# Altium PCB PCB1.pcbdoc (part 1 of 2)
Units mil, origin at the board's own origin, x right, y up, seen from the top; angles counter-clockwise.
Board outline 4205 x 5050 mil, 2 copper layers (Top Layer, Bottom Layer); 96 components, 86 nets, 386 pads, 487 vias.
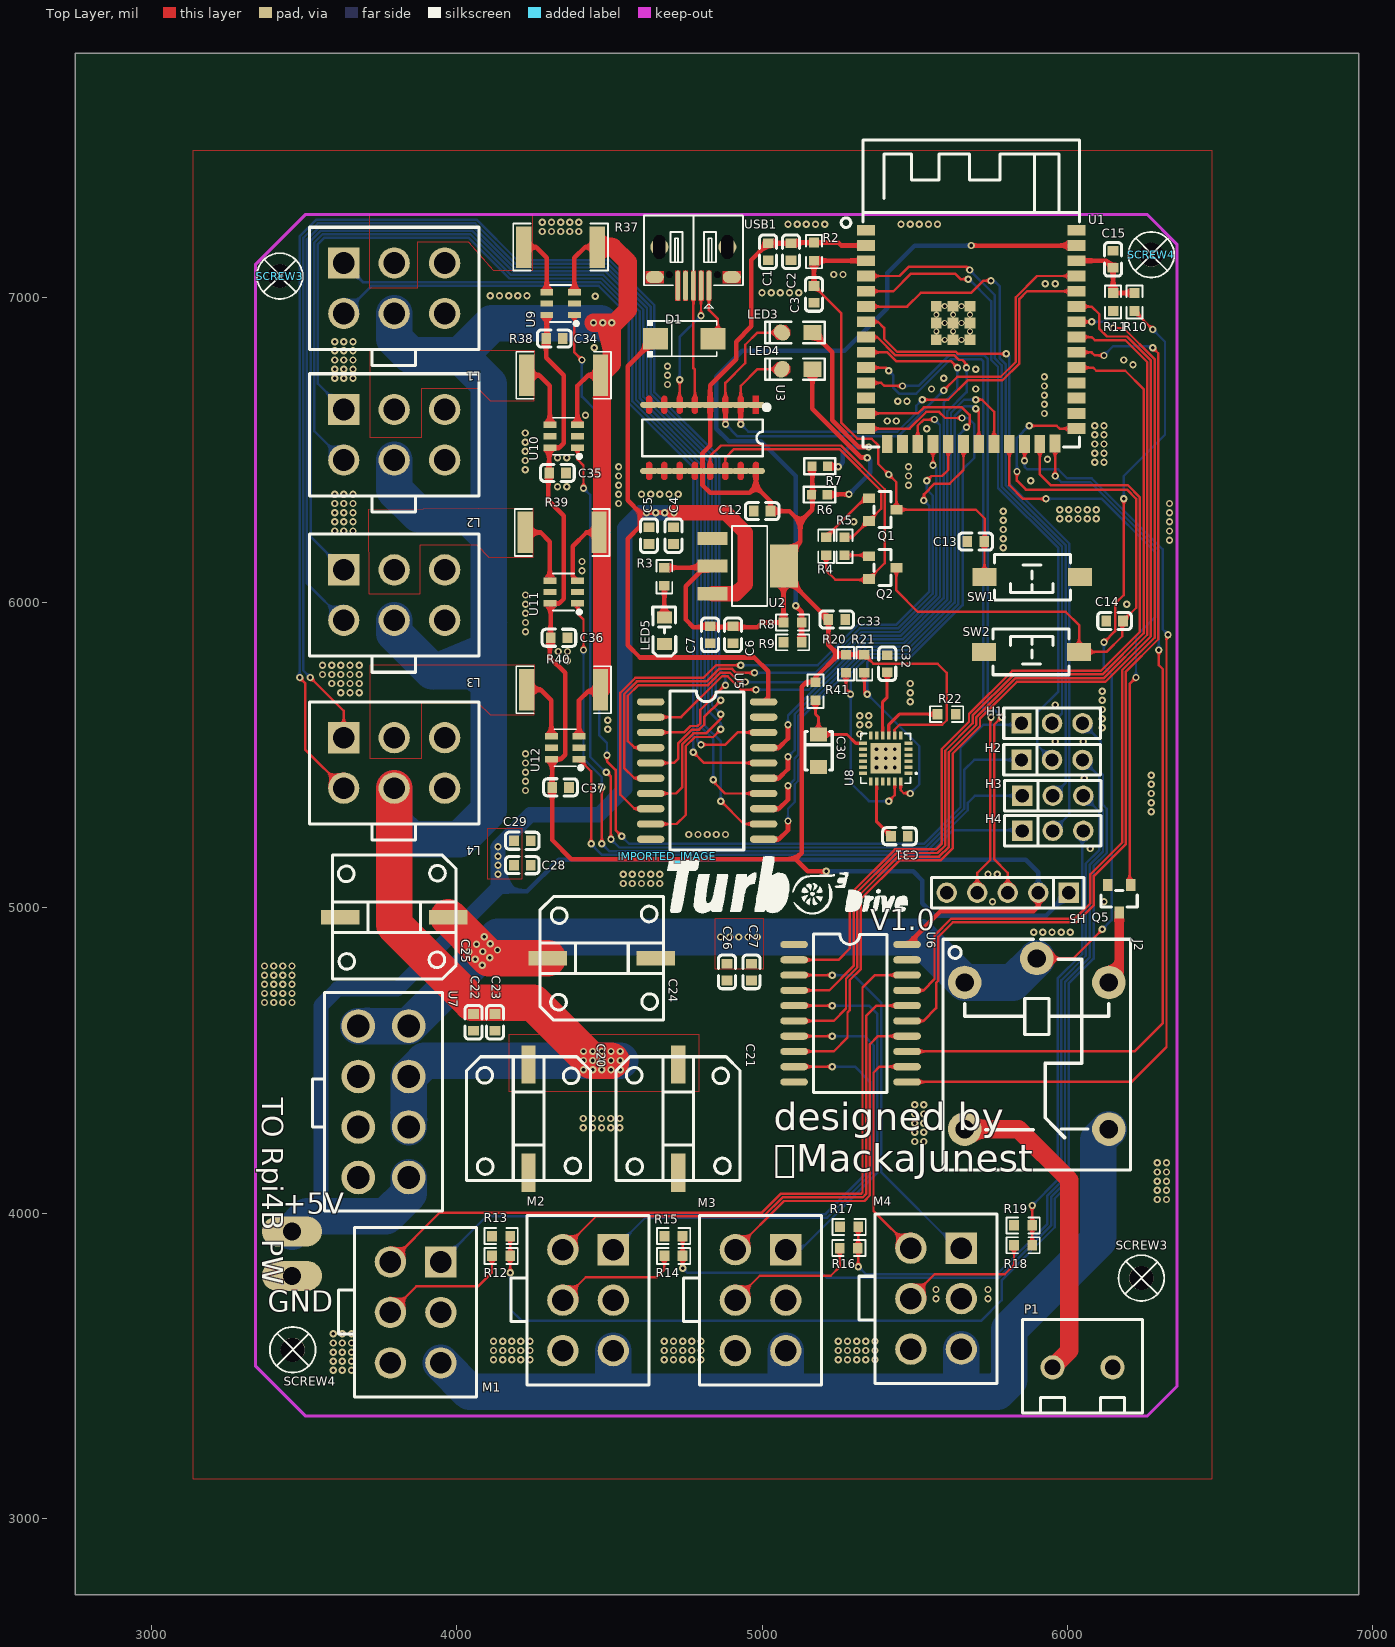
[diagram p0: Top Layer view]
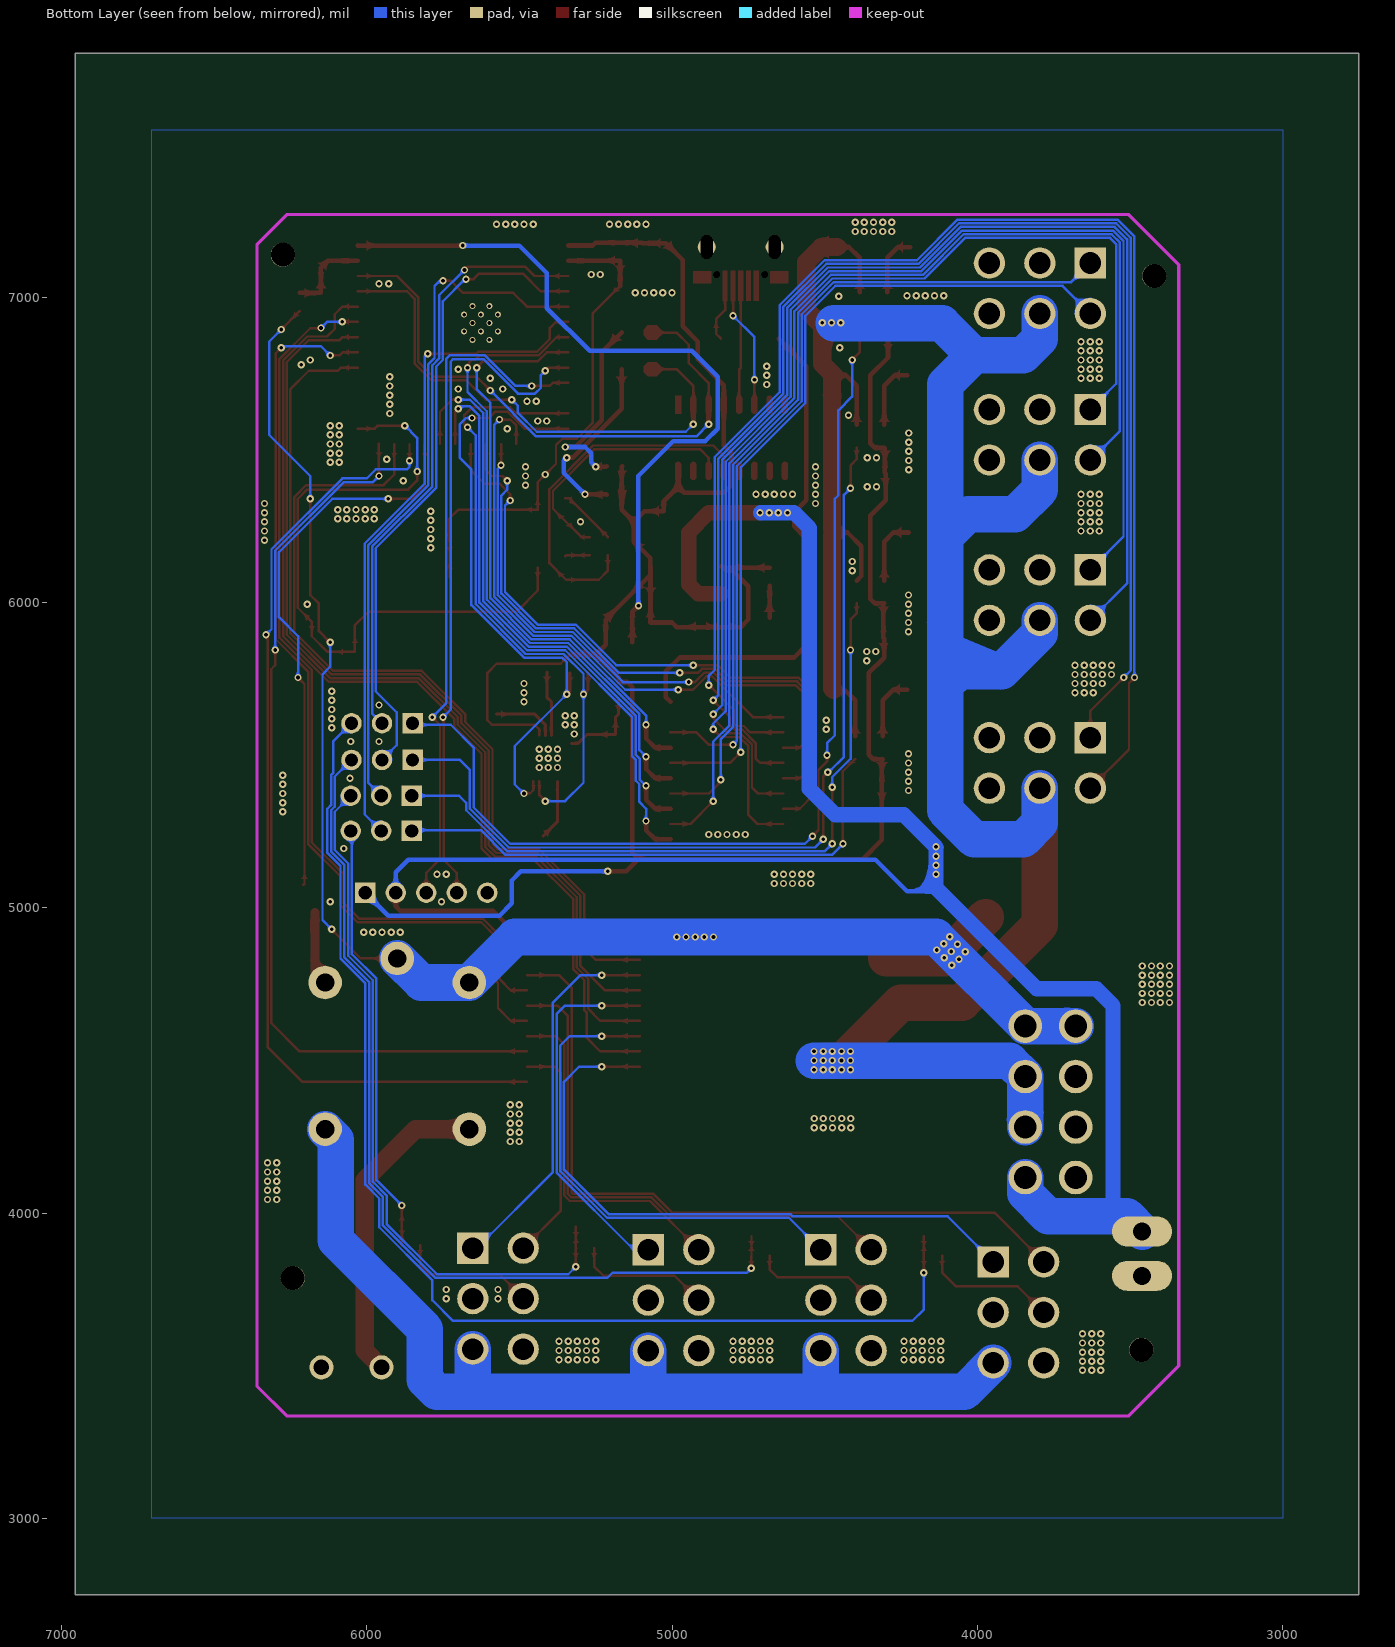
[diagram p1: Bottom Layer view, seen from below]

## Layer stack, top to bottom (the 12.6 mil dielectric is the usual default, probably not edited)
Top Layer: signal copper (thickness not stored)
Dielectric: dielectric 12.6, FR-4, Dk 4.8
Bottom Layer: signal copper (thickness not stored)

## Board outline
6955,2750 2750,2750 2750,7800 6955,7800

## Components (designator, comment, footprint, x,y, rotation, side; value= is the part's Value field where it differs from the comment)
C1 "={Value}/50V" C0603 5020,7150 r90 top
C2 "={Value}/50v" C0603 5095,7150 r90 top
C3 "CAP_0603" C0603 5170,7010 r90 top
C4 "CAP_0603" C0603 4710,6220 r90 top
C5 "CAP_0603" C0603 4630,6220 r90 top
C6 "CAP_0603" C0603 4905,5895 r90 top
C7 "CAP_0603" C0603 4830,5895 r90 top
C12 "CAP_0603" C0603 5000,6300 r180 top
C13 "CAP_0603" C0603 5700,6200 r0 top
C14 "CAP_0603" C0603 6155,5940 r0 top
C15 "CAP_0603" C0603 6150,7125 r90 top
C20 "330uf" CAP-T-10*10.5 4235,4310 r270 top
C21 "330uf" CAP-T-10*10.5 4725,4310 r270 top
C22 "CAP_0603" C0603 4055,4625 r270 top
C23 "CAP_0603" C0603 4125,4625 r270 top
C24 "330uf" CAP-T-10*10.5 4475,4835 r0 top
C25 "330uf" CAP-T-10*10.5 3795,4970 r180 top
C26 "CAP_0603" C0603 4885,4790 r270 top
C27 "CAP_0603" C0603 4965,4790 r270 top
C28 "CAP_0603" C0603 4215,5140 r0 top
C29 "CAP_0603" C0603 4215,5220 r0 top
C30 "0.1uF/4v/104" CAP-SMD_L3.2-W1.6 5185,5515 r270 top
C31 "2.2nF/50V" C0603 5450,5235 r180 top
C32 "0.1uF/2v/104" C0603 5410,5800 r270 top
C33 "10nF/4v" C0603 5245,5945 r0 top
C34 "CAP_0603" C0603 4320,6865 r0 top
C35 "CAP_0603" C0603 4330,6425 r0 top
C36 "CAP_0603" C0603 4335,5885 r0 top
C37 "CAP_0603" C0603 4340,5395 r0 top
D1 "SS14(1N5819)-SMA" SMA_L4.3-W2.7-LS5.1-RD 4745,6865 r0 top
H1 "HDR-M_2.54_1x3P" HDR-TH_3P-P2.54-V-M 5950,5605 r0 top
H2 "HDR-M_2.54_1x3P" HDR-TH_3P-P2.54-V-M 5950,5485 r0 top
H3 "HDR-M_2.54_1x3P" HDR-TH_3P-P2.54-V-M 5952.5,5367.5 r0 top
H4 "HDR-M_2.54_1x3P" HDR-TH_3P-P2.54-V-M 5952.5,5252.5 r0 top
H5 "HDR-M_2.54_1x5P" HDR-TH_5P-P2.54-V-M 5805,5050 r180 top
IMPORTED_IMAGE "IMPORTED_IMAGE" IMPORTED_IMAGE 4690,5170 r0 top
J2 "EM_BRAKE1" RELAY-TH_SRD-XXVDC-XL-C 5900,4555 r270 top
L1 "5557-2*3A" CONN-TH_5557-2X3A 3795,7030 r180 top
L2 "5557-2*3A" CONN-TH_5557-2X3A 3795,6550 r180 top
L3 "5557-2*3A" CONN-TH_5557-2X3A 3795,6025 r180 top
L4 "5557-2*3A" CONN-TH_5557-2X3A 3795,5475 r180 top
LED3 "LED-BLUE" "LED 0805B" 5115,6885 r180 top
LED4 "LED-YELLOW" "LED 0805Y" 5115,6765 r180 top
LED5 "LED_0805-R" LED_0805 4680,5910 r90 top
M1 "5557-2*3A" CONN-TH_5557-2X3A 3865,3675 r90 top
M2 "5557-2*3A" CONN-TH_5557-2X3A 4430,3715 r90 top
M3 "5557-2*3A" CONN-TH_5557-2X3A 4995,3715 r90 top
M4 "5557-2*3A" CONN-TH_5557-2X3A 5570,3720 r90 top
P1 "WJ126V-5.0-2P" CONN-TH_WJ126V-5.0-2P 6050,3495 r90 top
Q1 "S8050_SOT_NPN" S8050_SOT-23 5395,6310 r180 top
Q2 "S8050_SOT_NPN" S8050_SOT-23 5395,6120 r180 top
Q5 "S8050_SOT_NPN" S8050_SOT-23 6175,5030 r90 top
R2 "Res_0603" R0603 5170,7150 r90 top
R3 "Res_0603" R0603 4680,6085 r270 top
R4 "Res_0603" R0603 5210,6185 r90 top
R5 "Res_0603" R0603 5270,6185 r270 top
R6 "1K" "R 0603_L" 5188.12,6353.78 r180 top
R7 "1K" "R 0603_L" 5188.78,6446.87 r180 top
R8 "KNTC0603/10KF3950" R0603 5100,5935 r180 top
R9 "Res_0603" R0603 5100,5870 r0 top
R10 "Res_0603" R0603 6220,6985 r90 top
R11 "Res_0603" R0603 6150,6985 r270 top
R12 "Res_0603" R0603 4145,3860 r0 top
R13 "Res_0603" R0603 4145,3925 r180 top
R14 "Res_0603" R0603 4710,3860 r0 top
R15 "Res_0603" R0603 4710,3925 r180 top
R16 "Res_0603" R0603 5284.34,3885.77 r0 top
R17 "Res_0603" R0603 5285,3955 r180 top
R18 "Res_0603" R0603 5855,3895 r0 top
R19 "Res_0603" R0603 5855,3960 r180 top
R20 "4.7k" R0603 5275,5800 r90 top
R21 "4.7k" R0603 5335,5800 r90 top
R22 "4.7k" R0603 5604.66,5634.66 r180 top
R37 "0.01" R2512 4340,7165 r0 top
R38 "0.01" R2512 4350,6745 r0 top
R39 "0.01" R2512 4345,6230 r0 top
R40 "0.01" R2512 4350,5715 r0 top
R41 "Res_0603" R0603 5175,5710 r90 top
SCREW3 "M2螺丝" M2螺丝 3420,7070 r0 top
SCREW3 "M2螺丝" M2螺丝 6242.5,3787.5 r0 top
SCREW4 "M2螺丝" M2螺丝 6275,7140 r0 top
SCREW4 "M2螺丝" M2螺丝 3462.5,3552.5 r0 top
SW1 "3x6x5" "TSW SMD-3*6*2.5" 5883.65,6083.65 r180 top
SW2 "3x6x5" "TSW SMD-3*6*2.5" 5883.65,5838.65 r0 top
U1 "ESP32-S3-WROOM-1-N16R8" WIRELM-SMD_ESP32-S3-WROOM-1 5685,6870 r0 top
U2 "AMS1117-3.3_C6186" SOT-223-3_L6.5-W3.4-P2.30-LS7.0-BR 4955,6120 r180 top
U3 "CH340C" SOP16_L 4805,6540 r270 top
U5 "SN74HC244DWR" SOIC-20_L13.0-W7.6-P1.27-LS10.6-BL 4820,5450 r270 top
U6 "SN74HC244DWR" SOIC-20_L13.0-W7.6-P1.27-LS10.6-BL 5290,4655 r270 top
U7 "5557-2*4P直针座-黑色8芯" CONN-TH_5557-2-4P 3760,4365 r270 top
U8 "MPU-6050_C24112" QFN-24_L4.0-W4.0-P0.50-BL-EP2.6 5405,5490 r90 top
U9 "INA181A2IDBVR" SOT-23-6_L2.9-W1.6-P0.95-LS2.8-BL 4340,6980 r90 top
U10 "INA181A2IDBVR" SOT-23-6_L2.9-W1.6-P0.95-LS2.8-BL 4350,6545 r90 top
U11 "INA181A2IDBVR" SOT-23-6_L2.9-W1.6-P0.95-LS2.8-BL 4350,6035 r90 top
U12 "INA181A2IDBVR" SOT-23-6_L2.9-W1.6-P0.95-LS2.8-BL 4355,5525 r90 top
USB1 "MICRO USB" USB-MICRO_B 4775,7165 r180 top

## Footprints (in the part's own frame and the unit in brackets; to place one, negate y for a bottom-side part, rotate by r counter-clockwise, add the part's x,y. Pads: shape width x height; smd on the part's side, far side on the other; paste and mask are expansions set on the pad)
C0603 [mm]
  rect 0.8x0.9 smd: 1(-0.7,0) 2(0.7,0)
  silkscreen extent -1.41,-0.71 1.39,0.72
CAP-SMD_L3.2-W1.6 [mm]
  rect 1.2x1.4 smd: 1(-1.35,0) 2(1.35,0)
  silkscreen extent -1.6,-1.14 1.6,1.14
CAP-T-10*10.5 [mm]
  rect 3.2x1.2 smd: 1(-4.5,0) 2(4.5,0)
  silkscreen extent -5.15,-5.15 5.15,5.15
CONN-TH_5557-2-4P [mm]
  round 2.8 hole 1.9: 1(-6.3,2.1) 2(-2.1,2.1) 3(2.1,2.1) 4(6.3,2.1) 5(6.3,-2.1) 6(2.1,-2.1) 7(-2.1,-2.1) 8(-6.3,-2.1)
  silkscreen extent -9.1,-5.9 9.1,4.9
CONN-TH_5557-2X3A [mm]
  rect 2.6x2.6 hole 1.8: 1(4.2,-2.1)
  round 2.6 hole 1.8: 2(0,-2.1) 3(-4.2,-2.1) 5(0,2.1)
  round 2.6 hole 1.8 copper offset 0,0: 4(4.2,2.1) 6(-4.2,2.1)
  silkscreen extent -7.05,-5.08 7.05,6.42
CONN-TH_WJ126V-5.0-2P [mm]
  round 2 hole 1.3: 1(0,2.501) 2(0,-2.501)
  silkscreen extent -3.8,-5 4,5
HDR-TH_3P-P2.54-V-M [mm]
  rect 1.7x1.7 hole 1.1: 1(-2.54,0)
  round 1.7 hole 1.1: 2(0,0) 3(2.54,0)
  silkscreen extent -4.02,-1.27 4.02,1.27
HDR-TH_5P-P2.54-V-M [mm]
  rect 1.7x1.7 hole 1.1: 1(-5.08,0)
  round 1.7 hole 1.1: 2(-2.54,0) 3(0,0) 4(2.54,0) 5(5.08,0)
  silkscreen extent -6.35,-1.27 6.35,1.27
IMPORTED_IMAGE [mil]
  silkscreen extent 0,-191 787,0
"LED 0805B" [mil]
  rect 60x50 smd: 1(-50,0)
  oval 56.19x46.19 smd rot 140: 2(50,0)
  Top Layer region: 35.43,23.1 21.9,9.57 21.9,-9.57 35.43,-23.1 64.57,-23.1 78.1,-9.57 78.1,9.57 64.57,23.1
  silkscreen extent -90,-35 105,35
"LED 0805Y" [mil]
  rect 60x50 smd: 1(-50,0)
  oval 56.19x46.19 smd rot 60: 2(50,0)
  Top Layer region: 35.43,23.1 21.9,9.57 21.9,-9.57 35.43,-23.1 64.57,-23.1 78.1,-9.57 78.1,9.57 64.57,23.1
  silkscreen extent -90,-35 105,35
LED_0805 [mm]
  rect 1x1.25 smd: 1(-1.15,0.005) 2(1.05,0.005)
  silkscreen extent -2.15,-0.94 1.93,0.97
M2螺丝 [mm]
  round 2 hole 2: 1(0,0)
  silkscreen extent -1.9,-1.9 1.9,1.9
QFN-24_L4.0-W4.0-P0.50-BL-EP2.6 [mm]
  rect 0.28x0.665 smd: 1(-1.25,-1.908) 2(-0.75,-1.908) 3(-0.25,-1.908) 4(0.25,-1.908) 5(0.75,-1.908) 6(1.25,-1.908) 13(1.25,1.908) 14(0.75,1.908) 15(0.25,1.908) 16(-0.25,1.908) 17(-0.75,1.908) 18(-1.25,1.908)
  rect 0.665x0.28 smd: 7(1.908,-1.25) 8(1.908,-0.75) 9(1.908,-0.25) 10(1.908,0.25) 11(1.908,0.75) 12(1.908,1.25) 19(-1.908,1.25) 20(-1.908,0.75) 21(-1.908,0.25) 22(-1.908,-0.25) 23(-1.908,-0.75) 24(-1.908,-1.25)
  rect 2.55x2.55 smd: 25(0,0)
  silkscreen extent -2.08,-2.61 2.08,2.08
R0603 [mil]
  rect 31.75x34.02 smd: 1(-29.66,0) 2(29.66,0)
  silkscreen extent -55,-26 55,26
R2512 [mil]
  rect 50.49x136.06 smd: 1(-120.72,0) 2(120.72,0)
  silkscreen extent -155,-77 155,77
"R 0603_L" [mil]
  rect 30x30 smd: 1(-25.59,0) 2(25.59,0)
  silkscreen extent -51,-26 51,26
RELAY-TH_SRD-XXVDC-XL-C [mil]
  round 110 hole 60: 1(-200.79,-236.22) 2(279.53,-236.19) 3(279.53,236.2) 4(-200.79,236.22) 5(-279.53,0)
  silkscreen extent -342,-307 413,307
S8050_SOT-23 [mm]
  rect 1x0.8 smd: 1(1.15,-0.823) 2(1.15,1.077) 3(-1.15,0.127)
  silkscreen extent -0.7,-1.37 0.7,1.63
SMA_L4.3-W2.7-LS5.1-RD [mm]
  rect 2.1x1.8 smd: 1(-2.4,0) 2(2.4,0)
  silkscreen extent -3.08,-1.54 2.7,1.54
SOIC-20_L13.0-W7.6-P1.27-LS10.6-BL [mm]
  oval 0.6x2.3 smd: 1(-5.715,-4.7) 2(-4.445,-4.7) 3(-3.175,-4.7) 4(-1.905,-4.7) 5(-0.635,-4.7) 6(0.635,-4.7) 7(1.905,-4.7) 8(3.175,-4.7) 9(4.445,-4.7) 10(5.715,-4.7) 11(5.715,4.7) 12(4.445,4.7) 13(3.175,4.7) 14(1.905,4.7) 15(0.635,4.7) 16(-0.635,4.7) 17(-1.905,4.7) 18(-3.175,4.7) 19(-4.445,4.7) 20(-5.715,4.7)
  silkscreen extent -6.6,-3.1 6.6,3.05
SOP16_L [mm]
  oval 0.5x1.5 smd: 1(-2.752,4.445)
  oval 0.5x1.499 smd: 2(-2.752,3.175) 3(-2.752,1.905) 4(-2.752,0.635) 5(-2.752,-0.635) 6(-2.752,-1.905) 7(-2.752,-3.175) 8(-2.752,-4.445) 9(2.752,-4.445) 10(2.752,-3.175) 11(2.752,-1.905) 12(2.752,-0.635) 13(2.752,0.635) 14(2.752,1.905) 15(2.752,3.175) 16(2.752,4.445)
  Top Layer region: 3.252,-1.655 3.277,-1.656 3.302,-1.66 3.327,-1.666 3.351,-1.675 3.373,-1.686 3.395,-1.7 3.415,-1.715 3.433,-1.733 3.45,-1.752 3.464,-1.773 3.476,-1.795 3.486,-1.818 3.494,-1.842 3.499,-1.867 3.502,-1.892 3.502,-1.918 3.499,-1.943 3.494,-1.968 3.486,-1.992 3.476,-2.015 3.464,-2.037 3.45,-2.058 3.433,-2.077 3.415,-2.095 3.395,-2.11 3.373,-2.124 3.351,-2.135 3.327,-2.144 3.302,-2.15 3.277,-2.154 3.252,-2.155 2.252,-2.155 2.227,-2.154 2.202,-2.15 2.177,-2.144 2.153,-2.135 2.131,-2.124 2.109,-2.11 2.089,-2.095 2.071,-2.077 2.054,-2.058 2.04,-2.037 2.028,-2.015 2.018,-1.992 2.01,-1.968 2.005,-1.943 2.002,-1.918 2.002,-1.892 2.005,-1.867 2.01,-1.842 2.018,-1.818 2.028,-1.795 2.04,-1.773 2.054,-1.752 2.071,-1.733 2.089,-1.715 2.109,-1.7 2.131,-1.686 2.153,-1.675 2.177,-1.666 2.202,-1.66 2.227,-1.656 2.252,-1.655
  Top Layer region: 3.252,-2.925 3.277,-2.926 3.302,-2.93 3.327,-2.936 3.351,-2.945 3.373,-2.956 3.395,-2.97 3.415,-2.985 3.433,-3.003 3.45,-3.022 3.464,-3.043 3.476,-3.065 3.486,-3.088 3.494,-3.112 3.499,-3.137 3.502,-3.162 3.502,-3.188 3.499,-3.213 3.494,-3.238 3.486,-3.262 3.476,-3.285 3.464,-3.307 3.45,-3.328 3.433,-3.347 3.415,-3.365 3.395,-3.38 3.373,-3.394 3.351,-3.405 3.327,-3.414 3.302,-3.42 3.277,-3.424 3.252,-3.425 2.252,-3.425 2.227,-3.424 2.202,-3.42 2.177,-3.414 2.153,-3.405 2.131,-3.394 2.109,-3.38 2.089,-3.365 2.071,-3.347 2.054,-3.328 2.04,-3.307 2.028,-3.285 2.018,-3.262 2.01,-3.238 2.005,-3.213 2.002,-3.188 2.002,-3.162 2.005,-3.137 2.01,-3.112 2.018,-3.088 2.028,-3.065 2.04,-3.043 2.054,-3.022 2.071,-3.003 2.089,-2.985 2.109,-2.97 2.131,-2.956 2.153,-2.945 2.177,-2.936 2.202,-2.93 2.227,-2.926 2.252,-2.925
  Top Layer region: 3.252,-0.385 3.277,-0.386 3.302,-0.39 3.327,-0.396 3.351,-0.405 3.373,-0.416 3.395,-0.43 3.415,-0.445 3.433,-0.463 3.45,-0.482 3.464,-0.503 3.476,-0.525 3.486,-0.548 3.494,-0.572 3.499,-0.597 3.502,-0.622 3.502,-0.648 3.499,-0.673 3.494,-0.698 3.486,-0.722 3.476,-0.745 3.464,-0.767 3.45,-0.788 3.433,-0.807 3.415,-0.825 3.395,-0.84 3.373,-0.854 3.351,-0.865 3.327,-0.874 3.302,-0.88 3.277,-0.884 3.252,-0.885 2.252,-0.885 2.227,-0.884 2.202,-0.88 2.177,-0.874 2.153,-0.865 2.131,-0.854 2.109,-0.84 2.089,-0.825 2.071,-0.807 2.054,-0.788 2.04,-0.767 2.028,-0.745 2.018,-0.722 2.01,-0.698 2.005,-0.673 2.002,-0.648 2.002,-0.622 2.005,-0.597 2.01,-0.572 2.018,-0.548 2.028,-0.525 2.04,-0.503 2.054,-0.482 2.071,-0.463 2.089,-0.445 2.109,-0.43 2.131,-0.416 2.153,-0.405 2.177,-0.396 2.202,-0.39 2.227,-0.386 2.252,-0.385
  Top Layer region: 3.252,-4.195 3.277,-4.196 3.302,-4.2 3.327,-4.206 3.351,-4.215 3.373,-4.226 3.395,-4.24 3.415,-4.255 3.433,-4.273 3.45,-4.292 3.464,-4.313 3.476,-4.335 3.486,-4.358 3.494,-4.382 3.499,-4.407 3.502,-4.432 3.502,-4.458 3.499,-4.483 3.494,-4.508 3.486,-4.532 3.476,-4.555 3.464,-4.577 3.45,-4.598 3.433,-4.617 3.415,-4.635 3.395,-4.65 3.373,-4.664 3.351,-4.675 3.327,-4.684 3.302,-4.69 3.277,-4.694 3.252,-4.695 2.252,-4.695 2.227,-4.694 2.202,-4.69 2.177,-4.684 2.153,-4.675 2.131,-4.664 2.109,-4.65 2.089,-4.635 2.071,-4.617 2.054,-4.598 2.04,-4.577 2.028,-4.555 2.018,-4.532 2.01,-4.508 2.005,-4.483 2.002,-4.458 2.002,-4.432 2.005,-4.407 2.01,-4.382 2.018,-4.358 2.028,-4.335 2.04,-4.313 2.054,-4.292 2.071,-4.273 2.089,-4.255 2.109,-4.24 2.131,-4.226 2.153,-4.215 2.177,-4.206 2.202,-4.2 2.227,-4.196 2.252,-4.195
  Top Layer region: 3.252,0.885 3.277,0.884 3.302,0.88 3.327,0.874 3.351,0.865 3.373,0.854 3.395,0.84 3.415,0.825 3.433,0.807 3.45,0.788 3.464,0.767 3.476,0.745 3.486,0.722 3.494,0.698 3.499,0.673 3.502,0.648 3.502,0.622 3.499,0.597 3.494,0.572 3.486,0.548 3.476,0.525 3.464,0.503 3.45,0.482 3.433,0.463 3.415,0.445 3.395,0.43 3.373,0.416 3.351,0.405 3.327,0.396 3.302,0.39 3.277,0.386 3.252,0.385 2.252,0.385 2.227,0.386 2.202,0.39 2.177,0.396 2.153,0.405 2.131,0.416 2.109,0.43 2.089,0.445 2.071,0.463 2.054,0.482 2.04,0.503 2.028,0.525 2.018,0.548 2.01,0.572 2.005,0.597 2.002,0.622 2.002,0.648 2.005,0.673 2.01,0.698 2.018,0.722 2.028,0.745 2.04,0.767 2.054,0.788 2.071,0.807 2.089,0.825 2.109,0.84 2.131,0.854 2.153,0.865 2.177,0.874 2.202,0.88 2.227,0.884 2.252,0.885
  Top Layer region: 3.252,2.155 3.277,2.154 3.302,2.15 3.327,2.144 3.351,2.135 3.373,2.124 3.395,2.11 3.415,2.095 3.433,2.077 3.45,2.058 3.464,2.037 3.476,2.015 3.486,1.992 3.494,1.968 3.499,1.943 3.502,1.918 3.502,1.892 3.499,1.867 3.494,1.842 3.486,1.818 3.476,1.795 3.464,1.773 3.45,1.752 3.433,1.733 3.415,1.715 3.395,1.7 3.373,1.686 3.351,1.675 3.327,1.666 3.302,1.66 3.277,1.656 3.252,1.655 2.252,1.655 2.227,1.656 2.202,1.66 2.177,1.666 2.153,1.675 2.131,1.686 2.109,1.7 2.089,1.715 2.071,1.733 2.054,1.752 2.04,1.773 2.028,1.795 2.018,1.818 2.01,1.842 2.005,1.867 2.002,1.892 2.002,1.918 2.005,1.943 2.01,1.968 2.018,1.992 2.028,2.015 2.04,2.037 2.054,2.058 2.071,2.077 2.089,2.095 2.109,2.11 2.131,2.124 2.153,2.135 2.177,2.144 2.202,2.15 2.227,2.154 2.252,2.155
  Top Layer region: -2.252,-4.195 -2.227,-4.196 -2.202,-4.2 -2.177,-4.206 -2.153,-4.215 -2.131,-4.226 -2.109,-4.24 -2.089,-4.255 -2.071,-4.273 -2.054,-4.292 -2.04,-4.313 -2.028,-4.335 -2.018,-4.358 -2.01,-4.382 -2.005,-4.407 -2.002,-4.432 -2.002,-4.458 -2.005,-4.483 -2.01,-4.508 -2.018,-4.532 -2.028,-4.555 -2.04,-4.577 -2.054,-4.598 -2.071,-4.617 -2.089,-4.635 -2.109,-4.65 -2.131,-4.664 -2.153,-4.675 -2.177,-4.684 -2.202,-4.69 -2.227,-4.694 -2.252,-4.695 -3.252,-4.695 -3.277,-4.694 -3.302,-4.69 -3.327,-4.684 -3.351,-4.675 -3.373,-4.664 -3.395,-4.65 -3.415,-4.635 -3.433,-4.617 -3.45,-4.598 -3.464,-4.577 -3.476,-4.555 -3.486,-4.532 -3.494,-4.508 -3.499,-4.483 -3.502,-4.458 -3.502,-4.432 -3.499,-4.407 -3.494,-4.382 -3.486,-4.358 -3.476,-4.335 -3.464,-4.313 -3.45,-4.292 -3.433,-4.273 -3.415,-4.255 -3.395,-4.24 -3.373,-4.226 -3.351,-4.215 -3.327,-4.206 -3.302,-4.2 -3.277,-4.196 -3.252,-4.195
  Top Layer region: -2.252,-2.925 -2.227,-2.926 -2.202,-2.93 -2.177,-2.936 -2.153,-2.945 -2.131,-2.956 -2.109,-2.97 -2.089,-2.985 -2.071,-3.003 -2.054,-3.022 -2.04,-3.043 -2.028,-3.065 -2.018,-3.088 -2.01,-3.112 -2.005,-3.137 -2.002,-3.162 -2.002,-3.188 -2.005,-3.213 -2.01,-3.238 -2.018,-3.262 -2.028,-3.285 -2.04,-3.307 -2.054,-3.328 -2.071,-3.347 -2.089,-3.365 -2.109,-3.38 -2.131,-3.394 -2.153,-3.405 -2.177,-3.414 -2.202,-3.42 -2.227,-3.424 -2.252,-3.425 -3.252,-3.425 -3.277,-3.424 -3.302,-3.42 -3.327,-3.414 -3.351,-3.405 -3.373,-3.394 -3.395,-3.38 -3.415,-3.365 -3.433,-3.347 -3.45,-3.328 -3.464,-3.307 -3.476,-3.285 -3.486,-3.262 -3.494,-3.238 -3.499,-3.213 -3.502,-3.188 -3.502,-3.162 -3.499,-3.137 -3.494,-3.112 -3.486,-3.088 -3.476,-3.065 -3.464,-3.043 -3.45,-3.022 -3.433,-3.003 -3.415,-2.985 -3.395,-2.97 -3.373,-2.956 -3.351,-2.945 -3.327,-2.936 -3.302,-2.93 -3.277,-2.926 -3.252,-2.925
  Top Layer region: -2.252,-1.655 -2.227,-1.656 -2.202,-1.66 -2.177,-1.666 -2.153,-1.675 -2.131,-1.686 -2.109,-1.7 -2.089,-1.715 -2.071,-1.733 -2.054,-1.752 -2.04,-1.773 -2.028,-1.795 -2.018,-1.818 -2.01,-1.842 -2.005,-1.867 -2.002,-1.892 -2.002,-1.918 -2.005,-1.943 -2.01,-1.968 -2.018,-1.992 -2.028,-2.015 -2.04,-2.037 -2.054,-2.058 -2.071,-2.077 -2.089,-2.095 -2.109,-2.11 -2.131,-2.124 -2.153,-2.135 -2.177,-2.144 -2.202,-2.15 -2.227,-2.154 -2.252,-2.155 -3.252,-2.155 -3.277,-2.154 -3.302,-2.15 -3.327,-2.144 -3.351,-2.135 -3.373,-2.124 -3.395,-2.11 -3.415,-2.095 -3.433,-2.077 -3.45,-2.058 -3.464,-2.037 -3.476,-2.015 -3.486,-1.992 -3.494,-1.968 -3.499,-1.943 -3.502,-1.918 -3.502,-1.892 -3.499,-1.867 -3.494,-1.842 -3.486,-1.818 -3.476,-1.795 -3.464,-1.773 -3.45,-1.752 -3.433,-1.733 -3.415,-1.715 -3.395,-1.7 -3.373,-1.686 -3.351,-1.675 -3.327,-1.666 -3.302,-1.66 -3.277,-1.656 -3.252,-1.655
  Top Layer region: -2.252,2.155 -2.227,2.154 -2.202,2.15 -2.177,2.144 -2.153,2.135 -2.131,2.124 -2.109,2.11 -2.089,2.095 -2.071,2.077 -2.054,2.058 -2.04,2.037 -2.028,2.015 -2.018,1.992 -2.01,1.968 -2.005,1.943 -2.002,1.918 -2.002,1.892 -2.005,1.867 -2.01,1.842 -2.018,1.818 -2.028,1.795 -2.04,1.773 -2.054,1.752 -2.071,1.733 -2.089,1.715 -2.109,1.7 -2.131,1.686 -2.153,1.675 -2.177,1.666 -2.202,1.66 -2.227,1.656 -2.252,1.655 -3.252,1.655 -3.277,1.656 -3.302,1.66 -3.327,1.666 -3.351,1.675 -3.373,1.686 -3.395,1.7 -3.415,1.715 -3.433,1.733 -3.45,1.752 -3.464,1.773 -3.476,1.795 -3.486,1.818 -3.494,1.842 -3.499,1.867 -3.502,1.892 -3.502,1.918 -3.499,1.943 -3.494,1.968 -3.486,1.992 -3.476,2.015 -3.464,2.037 -3.45,2.058 -3.433,2.077 -3.415,2.095 -3.395,2.11 -3.373,2.124 -3.351,2.135 -3.327,2.144 -3.302,2.15 -3.277,2.154 -3.252,2.155
  Top Layer region: -2.252,3.425 -2.227,3.424 -2.202,3.42 -2.177,3.414 -2.153,3.405 -2.131,3.394 -2.109,3.38 -2.089,3.365 -2.071,3.347 -2.054,3.328 -2.04,3.307 -2.028,3.285 -2.018,3.262 -2.01,3.238 -2.005,3.213 -2.002,3.188 -2.002,3.162 -2.005,3.137 -2.01,3.112 -2.018,3.088 -2.028,3.065 -2.04,3.043 -2.054,3.022 -2.071,3.003 -2.089,2.985 -2.109,2.97 -2.131,2.956 -2.153,2.945 -2.177,2.936 -2.202,2.93 -2.227,2.926 -2.252,2.925 -3.252,2.925 -3.277,2.926 -3.302,2.93 -3.327,2.936 -3.351,2.945 -3.373,2.956 -3.395,2.97 -3.415,2.985 -3.433,3.003 -3.45,3.022 -3.464,3.043 -3.476,3.065 -3.486,3.088 -3.494,3.112 -3.499,3.137 -3.502,3.162 -3.502,3.188 -3.499,3.213 -3.494,3.238 -3.486,3.262 -3.476,3.285 -3.464,3.307 -3.45,3.328 -3.433,3.347 -3.415,3.365 -3.395,3.38 -3.373,3.394 -3.351,3.405 -3.327,3.414 -3.302,3.42 -3.277,3.424 -3.252,3.425
  Top Layer region: -2.252,-0.385 -2.227,-0.386 -2.202,-0.39 -2.177,-0.396 -2.153,-0.405 -2.131,-0.416 -2.109,-0.43 -2.089,-0.445 -2.071,-0.463 -2.054,-0.482 -2.04,-0.503 -2.028,-0.525 -2.018,-0.548 -2.01,-0.572 -2.005,-0.597 -2.002,-0.622 -2.002,-0.648 -2.005,-0.673 -2.01,-0.698 -2.018,-0.722 -2.028,-0.745 -2.04,-0.767 -2.054,-0.788 -2.071,-0.807 -2.089,-0.825 -2.109,-0.84 -2.131,-0.854 -2.153,-0.865 -2.177,-0.874 -2.202,-0.88 -2.227,-0.884 -2.252,-0.885 -3.252,-0.885 -3.277,-0.884 -3.302,-0.88 -3.327,-0.874 -3.351,-0.865 -3.373,-0.854 -3.395,-0.84 -3.415,-0.825 -3.433,-0.807 -3.45,-0.788 -3.464,-0.767 -3.476,-0.745 -3.486,-0.722 -3.494,-0.698 -3.499,-0.673 -3.502,-0.648 -3.502,-0.622 -3.499,-0.597 -3.494,-0.572 -3.486,-0.548 -3.476,-0.525 -3.464,-0.503 -3.45,-0.482 -3.433,-0.463 -3.415,-0.445 -3.395,-0.43 -3.373,-0.416 -3.351,-0.405 -3.327,-0.396 -3.302,-0.39 -3.277,-0.386 -3.252,-0.385
  Top Layer region: -2.252,0.885 -2.227,0.884 -2.202,0.88 -2.177,0.874 -2.153,0.865 -2.131,0.854 -2.109,0.84 -2.089,0.825 -2.071,0.807 -2.054,0.788 -2.04,0.767 -2.028,0.745 -2.018,0.722 -2.01,0.698 -2.005,0.673 -2.002,0.648 -2.002,0.622 -2.005,0.597 -2.01,0.572 -2.018,0.548 -2.028,0.525 -2.04,0.503 -2.054,0.482 -2.071,0.463 -2.089,0.445 -2.109,0.43 -2.131,0.416 -2.153,0.405 -2.177,0.396 -2.202,0.39 -2.227,0.386 -2.252,0.385 -3.252,0.385 -3.277,0.386 -3.302,0.39 -3.327,0.396 -3.351,0.405 -3.373,0.416 -3.395,0.43 -3.415,0.445 -3.433,0.463 -3.45,0.482 -3.464,0.503 -3.476,0.525 -3.486,0.548 -3.494,0.572 -3.499,0.597 -3.502,0.622 -3.502,0.648 -3.499,0.673 -3.494,0.698 -3.486,0.722 -3.476,0.745 -3.464,0.767 -3.45,0.788 -3.433,0.807 -3.415,0.825 -3.395,0.84 -3.373,0.854 -3.351,0.865 -3.327,0.874 -3.302,0.88 -3.277,0.884 -3.252,0.885
  Top Layer region: 3.252,3.425 3.277,3.424 3.302,3.42 3.327,3.414 3.351,3.405 3.373,3.394 3.395,3.38 3.415,3.365 3.433,3.347 3.45,3.328 3.464,3.307 3.476,3.285 3.486,3.262 3.494,3.238 3.499,3.213 3.502,3.188 3.502,3.162 3.499,3.137 3.494,3.112 3.486,3.088 3.476,3.065 3.464,3.043 3.45,3.022 3.433,3.003 3.415,2.985 3.395,2.97 3.373,2.956 3.351,2.945 3.327,2.936 3.302,2.93 3.277,2.926 3.252,2.925 2.252,2.925 2.227,2.926 2.202,2.93 2.177,2.936 2.153,2.945 2.131,2.956 2.109,2.97 2.089,2.985 2.071,3.003 2.054,3.022 2.04,3.043 2.028,3.065 2.018,3.088 2.01,3.112 2.005,3.137 2.002,3.162 2.002,3.188 2.005,3.213 2.01,3.238 2.018,3.262 2.028,3.285 2.04,3.307 2.054,3.328 2.071,3.347 2.089,3.365 2.109,3.38 2.131,3.394 2.153,3.405 2.177,3.414 2.202,3.42 2.227,3.424 2.252,3.425
  Top Layer region: 3.252,4.695 3.277,4.694 3.302,4.69 3.327,4.684 3.351,4.675 3.373,4.664 3.395,4.65 3.415,4.635 3.433,4.617 3.45,4.598 3.464,4.577 3.476,4.555 3.486,4.532 3.494,4.508 3.499,4.483 3.502,4.458 3.502,4.432 3.499,4.407 3.494,4.382 3.486,4.358 3.476,4.335 3.464,4.313 3.45,4.292 3.433,4.273 3.415,4.255 3.395,4.24 3.373,4.226 3.351,4.215 3.327,4.206 3.302,4.2 3.277,4.196 3.252,4.195 2.252,4.195 2.227,4.196 2.202,4.2 2.177,4.206 2.153,4.215 2.131,4.226 2.109,4.24 2.089,4.255 2.071,4.273 2.054,4.292 2.04,4.313 2.028,4.335 2.018,4.358 2.01,4.382 2.005,4.407 2.002,4.432 2.002,4.458 2.005,4.483 2.01,4.508 2.018,4.532 2.028,4.555 2.04,4.577 2.054,4.598 2.071,4.617 2.089,4.635 2.109,4.65 2.131,4.664 2.153,4.675 2.177,4.684 2.202,4.69 2.227,4.694 2.252,4.695
  Top Layer region: -3.502,4.195 -3.502,4.695 -2.002,4.695 -2.002,4.195
  silkscreen extent -2.69,-5 1.52,5.49
SOT-23-6_L2.9-W1.6-P0.95-LS2.8-BL [mil]
  rect 20.95x42.2 smd: 1(-37.4,-45.24) 2(0,-45.24) 3(37.4,-45.24) 4(37.4,45.24) 5(0,45.24) 6(-37.4,45.24)
  silkscreen extent -72,-57 61,35
SOT-223-3_L6.5-W3.4-P2.30-LS7.0-BR [mm]
  rect 2.5x1.1 smd: 1(2.97,-2.3) 2(2.97,0) 3(2.97,2.3)
  rect 2.34x3.6 smd: 4(-2.97,0)
  silkscreen extent -1.57,-3.33 1.37,3.33
"TSW SMD-3*6*2.5" [mm]
  rect 2x1.5 smd: 1(-3.996,-0.02) 2(3.937,0)
  silkscreen extent -3.21,-1.9 3.09,1.9
USB-MICRO_B [mm]
  round 0.35 hole 0.55 slot 0.555 at 90 deg unplated: 0(2,2.294) 8(-2,2.294)
  oval 0.394x2.5 smd: 1(-1.295,3.217) 2(-0.647,3.217) 3(0,3.217) 4(0.648,3.217) 5(1.295,3.217)
  oval 1.5x1 smd: 6(3.2,2.5) 7(-3.2,2.5)
  round 1.5 hole 1 slot 2 at 90 deg: 9(-2.825,-0.006) 10(2.825,-0.006)
  Top Layer region: 0.845,1.967 0.451,1.967 0.451,4.467 0.845,4.467
  Top Layer region: 0.197,1.967 -0.197,1.967 -0.197,4.467 0.197,4.467
  Top Layer region: -0.451,1.967 -0.845,1.967 -0.845,4.467 -0.451,4.467
  Top Layer region: -1.099,1.967 -1.492,1.967 -1.492,4.467 -1.099,4.467
  Top Layer region: 1.492,1.967 1.099,1.967 1.099,4.467 1.492,4.467
  Top Layer region: 2.45,2 2.45,3 3.95,3 3.95,2
  Top Layer region: -3.95,2 -3.95,3 -2.45,3 -2.45,2
  silkscreen extent -4.14,-2.63 4.11,5.08
WIRELM-SMD_ESP32-S3-WROOM-1 [mm]
  rect 1.5x0.9 smd: 1(-8.75,8.895) 2(-8.75,7.625) 3(-8.75,6.355) 4(-8.75,5.085) 5(-8.75,3.815) 6(-8.75,2.545) 7(-8.75,1.275) 8(-8.75,0.005) 9(-8.75,-1.265) 10(-8.75,-2.535) 11(-8.75,-3.805) 12(-8.75,-5.075) 13(-8.75,-6.345) 14(-8.75,-7.615) 27(8.75,-7.615) 28(8.75,-6.345) 29(8.75,-5.075) 30(8.75,-3.805) 31(8.75,-2.535) 32(8.75,-1.265) 33(8.75,0.005) 34(8.75,1.275) 35(8.75,2.545) 36(8.75,3.815) 37(8.75,5.085) 38(8.75,6.355) 39(8.75,7.625) 40(8.75,8.895)
  rect 0.9x1.5 smd: 15(-6.985,-8.895) 16(-5.715,-8.895) 17(-4.445,-8.895) 18(-3.175,-8.895) 19(-1.905,-8.895) 20(-0.635,-8.895) 21(0.635,-8.895) 22(1.905,-8.895) 23(3.175,-8.895) 24(4.445,-8.895) 25(5.715,-8.895) 26(6.985,-8.865)
  rect 0.9x0.9 smd: 41(-2.9,-0.225) 41(-2.9,1.175) 41(-2.9,2.575) 41(-1.5,-0.225) 41(-1.5,1.175) 41(-1.5,2.575) 41(-0.1,-0.225) 41(-0.1,1.175) 41(-0.1,2.575)
  silkscreen extent -10.81,-9.14 9.02,16.39

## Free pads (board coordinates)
  oval 196.85x98.43 hole 59.06: 1(3460,3795) 1(3460,3940)

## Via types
v1: diameter 24.02, hole 12.01, Top Layer to Bottom Layer, 475 vias
v2: diameter 19.69, hole 11.81, Top Layer to Bottom Layer, 12 vias

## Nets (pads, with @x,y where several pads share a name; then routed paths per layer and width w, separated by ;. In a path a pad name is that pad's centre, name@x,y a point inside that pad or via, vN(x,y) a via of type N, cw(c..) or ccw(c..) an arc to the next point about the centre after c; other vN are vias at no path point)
3V3: C1.2 C2.2 C6.2 C7.2 C12.1 C33.1 C34.1 C35.1 C36.1 C37.1 H5.1 R2.2 R3.1 R6.2 R7.2 R8.2 R20.2 R21.2 R41.2 U1.2 U2.2 U2.4 U3.4 U3.16 U8.8 U9.6 U10.6 U11.6 U12.6 | length 8548.2
  Top Layer w8: R21.2@5335,5829.66 5364.66,5800 5575,5800 5605,5770 5605,5615 5590,5600 5450.37,5600 5434.53,5584.16 U8.8@5434.53,5565.1
  Top Layer w15: U9.6@4294.76,6942.6 4294.76,6867.32 C34.1@4292.44,6865 4292.44,6802.56 4350,6745 4350,6522.24 4335.36,6507.6 U10.6@4304.76,6507.6 4302.44,6505.28 C35.1@4302.44,6425 4300,6422.56 4300,6335 4350,6285 4350,6012.24 4335.36,5997.6 U11.6@4304.76,5997.6 4307.44,5994.92 C36.1@4307.44,5885 4305,5882.56 4305,5820 4355,5770 4355,5502.24 4340.36,5487.6 U12.6@4309.76,5487.6 4312.44,5484.92 C37.1@4312.44,5395 4312.44,5222.56 4375,5160 5110,5160 ; R3.1@4680,6114.66 U2.2@4832.73,6114.66 ; U2.2@4838.07,6120 U2.2@4832.73,6114.66 ; U3.16@4980,6431.65 4980,6380 ; R7.2@5163.19,6446.87 5165,6445.06 5165,6305 5125,6265 ; v1(5210,5120) 5150,5120 5110,5160 ; R21.2@5335,5829.66 5334.66,5830 5250,5830 ; U1.2@5340.51,7170.19 5260,7170.19 5250.53,7179.66 R2.2@5170,7179.66 5097.1,7179.66 C2.2@5095,7177.56 C1.2@5020,7177.56 4965,7122.56 4965,6905 4915,6855 4915,6797.36 4830,6712.36 U3.4@4830,6648.35 4830,6515 4805,6490 4805,6385 4830,6360 4960,6360 4980,6380 ; U2.2@4832.73,6114.66 4823.07,6105 4800.56,6105 4750,6054.44 4750,5945 4775,5920 4985,5920 5000,5935 R8.2@5070.34,5935 5070.34,6118.41 U2.4@5071.93,6120 ; 4980,6380 5027.56,6332.44 C12.1@5027.56,6300 5090,6300 5125,6265 ; U2.4@5071.93,6120 5071.93,6146.93 5125,6200 5125,6265 ; U2.4@5071.93,6120 5071.93,6090.51 C33.1@5217.44,5945 5217.44,5862.56 5250,5830 ; 5110,5160 5130,5180 5130,5725 5144.66,5739.66 R41.2@5175,5739.66 5175,5755 5250,5830
  Bottom Layer w15: v1(5210,5120) 5495,5120 5525,5090 5525,5015 5565,4975 5930,4975 H5.1@6005,5050
7.4VDC: C20.1 C21.1 C22.1 C23.1 L1.5 L2.5 L3.5 L4.5 R37.2 R38.2 R39.2 R40.2 U7.2 U7.3 U9.3 U10.3 U11.3 U12.3 | length 8949.4
  Top Layer w15: U9.3@4385.24,7017.4 4385.24,7130.24 4420,7165 R37.2@4460.72,7165 ; U11.3@4395.24,6072.4 4380.24,6087.4 4380.24,6185.24 4425,6230 R39.2@4465.72,6230 ; U10.3@4395.24,6582.4 4395.24,6710.24 4430,6745 R38.2@4470.72,6745 ; U12.3@4400.24,5562.4 4400.24,5680.24 4430,5710 R40.2@4465.72,5710
  Top Layer w60: v1(4447.66,6916.96) v1(4477.66,6916.96) v1(4507.66,6916.96) ; R37.2@4460.72,7165 4510.72,7165 4560,7115.72 4560,6959.3 4517.66,6916.96 v1(4507.66,6916.96) ; R40.2@4470.72,5715 4475.72,5720 4475.72,6220 R39.2@4465.72,6230 4475.72,6240 4475.72,6740 R38.2@4470.72,6745 4507.66,6781.93 v1(4507.66,6916.96)
  Top Layer w120: L4.5@3795,5392.33 3795,4945 4050,4690 4250,4690 4440,4500 v1(4475,4500) v1(4505,4500)
  Bottom Layer w120: L4.5@3795,5392.33 3795,5279.18 3849.18,5225 4010,5225 4105,5320 4105,5730 ; L3.5@3795,5942.33 3795,5900 3920,5775 4060,5775 4105,5730 ; L2.5@3795,6467.33 3795,6370 3875,6290 4030,6290 4105,6215 ; L1.5@3795,6947.33 3795,6865 3850,6810 4010,6810 ; U7.3@3842.68,4282.32 U7.2@3842.68,4447.68 3893.67,4498.67 ; v1@4470,6915 4115,6915 4010,6810 ; v1(4535,4500) v1(4505,4500) v1(4475,4500) v1(4445,4500) v1(4415,4500) ; 3893.67,4498.67 v1(4415,4500) ; 3893.67,4498.67 3895,4500 v1(4415,4500) ; 4010,6810 4105,6715 4105,6215 ; 4105,5730 4105,6215
  other v1: 4415,4470 4445,4470 4475,4470 4505,4470 4535,4470 4415,4530 4445,4530 4475,4530 4505,4530 4535,4530
12.6VDC: C24.1 C25.1 C26.1 C27.1 J2.1 J2.5 R10.1 U7.1 U7.8 | length 5247.8
  Top Layer w8: J2.5@5900,4834.53 6019.53,4834.53 v1(6115,4930) ; v1(6120,5870) 6156.81,5906.81 6156.81,5996.81 6185,6025 v1(6185,6340) ; R10.1@6220,6955.34 6280,6895.34 v1(6280,6895)
  Top Layer w120: C25.1@3972.17,4970 v1(4085,4857.17) 4085,4855 4105,4835 C24.1@4297.83,4835
  Bottom Layer w8: v1(6115,4930) 6145,4960 6145,5765 6120,5790 v1(6120,5870) ; v1(6185,6340) 6185,6415 6320,6550 6320,6855 v1(6280,6895)
  Bottom Layer w120: U7.8@3677.32,4613.03 U7.1@3842.68,4613.03 4134.65,4905 v1(4863.98,4905) v1(4893.98,4905) v1(4923.98,4905) v1(4953.98,4905) v1(4983.98,4905) 5514.57,4905 J2.1@5663.78,4755.79 5821.26,4755.79 J2.5@5900,4834.53
  other v1: 4083.12,4812.18 4060,4832.17 4108.12,4837.18 4039.69,4856.08 4133.12,4862.18 4064.69,4881.08 4110,4882.17 4089.69,4906.08
$1N1222: LED5.2 R3.2 | length 104.1
  Top Layer w15: LED5.2@4679.8,5951.34 4680,5951.54 R3.2@4680,6055.34
$1N2133: Q1.1 R4.2 | length 192.6
  Top Layer w8: R4.2@5210,6214.66 5337.74,6342.4 Q1.1@5349.72,6342.4
$1N2136: Q2.1 R5.2 | length 80.9
  Top Layer w8: R5.2@5270,6155.34 5346.79,6155.34 Q2.1@5349.72,6152.4
$1N2741: LED4.1 R6.1 | length 601
  Top Layer w15: LED4.1@5165,6765 5165,6635.39 5325.39,6475 v1(5345,6475) ; R6.1@5213.71,6353.78 5214.93,6355 v1(5285,6355)
  Bottom Layer w15: v1(5285,6355) 5355,6425 5355,6465 v1(5345,6475)
$1N2742: LED3.1 R7.1 | length 651.7
  Top Layer w15: LED3.1@5165,6885 5230,6820 5230,6597.26 5317.26,6510 v1(5350,6510) ; R7.1@5214.37,6446.87 5216.24,6445 v1(5250,6445)
  Bottom Layer w15: v1(5250,6445) 5265,6460 5265,6490 5285,6510 v1(5350,6510)
$1N4890: D1.2 USB1.1 | length 192.2
  Top Layer w8: USB1.1@4825.99,7038.35 4825.99,6958.35 4855.51,6928.83 4855.51,6881.02 D1.2@4839.49,6865
$1N6785: H1.2 U1.4 | length 1979.8
  Top Layer w8: U1.4@5340.51,7070.19 5450.19,7070.19 5480,7100 5670,7100 v1(5680,7090)
  Bottom Layer w8: v1(5680,7090) 5763,7007 5763,6800.03 5785,6778.03 5785,6381.06 5982.54,6183.52 5982.54,5637.54 H1.2@5950,5605
$1N6797: H2.2 U1.5 | length 2113.7
  Top Layer w8: U1.5@5340.51,7020.19 5430.19,7020.19 5488,7078 5632,7078 5650,7060 v1(5675,7060)
  Bottom Layer w8: v1(5675,7060) 5678.03,7060 5751,6987.03 5751,6795.06 5773,6773.06 5773,6376.09 5970.54,6178.55 5970.54,5709.41 5901.54,5640.41 5901.54,5533.46 H2.2@5950,5485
